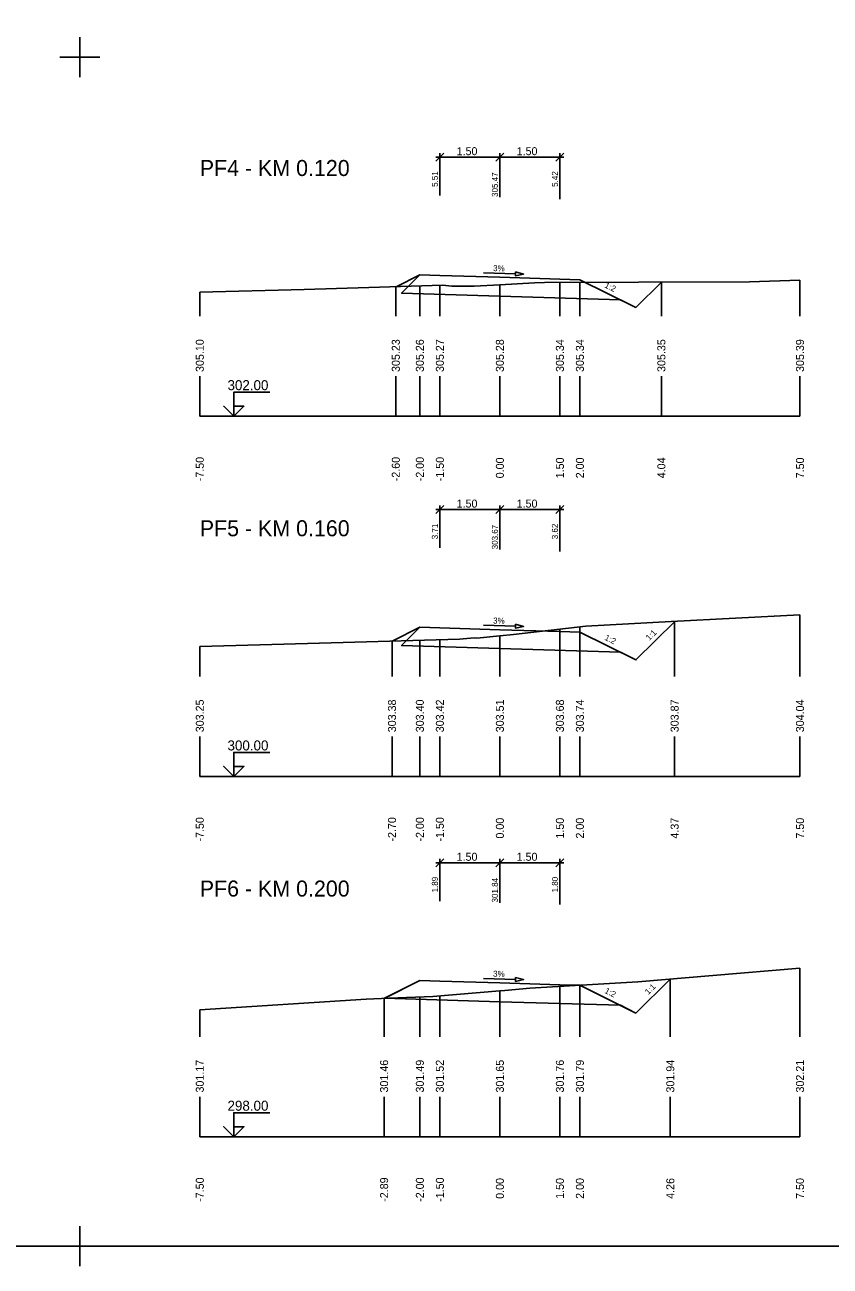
# Model space of a CAD drawing. Extents: x -5 to 1265, y -2 to 602.
# Drawn here: x 196.3 to 397.5, y -2.3 to 307.8 of the extents above; entities that cross this region are included whole.
import ezdxf

# ---------------------------------------------------------------- set-up
doc = ezdxf.new("R2010")
doc.units = 0
for name, color, linetype in [('KOTA', 7, 'Continuous'), ('KOTA_DELKY', 7, 'Continuous'), ('KOTA_DELKY_CONT', 7, 'Continuous'), ('NS_TELESO_VOZOVKY', 7, 'Continuous'), ('NS_V_PF', 7, 'Continuous'), ('REZY_PF_PUVODNI', 7, 'Continuous'), ('SESTAVY_REZU_PF', 7, 'Continuous'), ('SKLON', 7, 'Continuous'), ('SVK', 7, 'Continuous')]:
    doc.layers.add(name, color=color, linetype=linetype)

msp = doc.modelspace()

# ---------------------------------------------------------------- linework, layer by layer
for p, q in [((210, 304.67), (210, 294.67)), ((210, 304.67), (210, 294.67)), ((210, 304.67), (210, 294.67)), ((210, 304.67), (210, 294.67)), ((210, 304.67), (210, 294.67)), ((210, 304.67), (210, 294.67)), ((210, 304.67), (210, 294.67)), ((210, 304.67), (210, 294.67)), ((210, 304.67), (210, 294.67)), ((210, 304.67), (210, 294.67)), ((210, 304.67), (210, 294.67)), ((210, 304.67), (210, 294.67)), ((210, 304.67), (210, 294.67)), ((210, 304.67), (210, 294.67)), ((210, 304.67), (210, 294.67)), ((210, 304.67), (210, 294.67)), ((210, 304.67), (210, 294.67)), ((210, 304.67), (210, 294.67)), ((210, 304.67), (210, 294.67)), ((210, 304.67), (210, 294.67)), ((210, 304.67), (210, 294.67)), ((210, 304.67), (210, 294.67)), ((210, 304.67), (210, 294.67)), ((210, 304.67), (210, 294.67)), ((210, 304.67), (210, 294.67)), ((210, 304.67), (210, 294.67)), ((210, 304.67), (210, 294.67)), ((210, 304.67), (210, 294.67)), ((210, 304.67), (210, 294.67)), ((210, 304.67), (210, 294.67)), ((210, 304.67), (210, 294.67)), ((210, 304.67), (210, 294.67)), ((210, 304.67), (210, 294.67)), ((210, 304.67), (210, 294.67)), ((210, 304.67), (210, 294.67)), ((210, 304.67), (210, 294.67)), ((210, 304.67), (210, 294.67)), ((210, 304.67), (210, 294.67)), ((210, 304.67), (210, 294.67)), ((210, 304.67), (210, 294.67)), ((210, 304.67), (210, 294.67)), ((210, 304.67), (210, 294.67)), ((210, 304.67), (210, 294.67)), ((210, 304.67), (210, 294.67)), ((210, 304.67), (210, 294.67)), ((210, 304.67), (210, 294.67)), ((210, 304.67), (210, 294.67)), ((210, 304.67), (210, 294.67)), ((210, 304.67), (210, 294.67)), ((210, 304.67), (210, 294.67)), ((210, 304.67), (210, 294.67)), ((210, 304.67), (210, 294.67)), ((210, 304.67), (210, 294.67)), ((210, 304.67), (210, 294.67)), ((210, 304.67), (210, 294.67)), ((210, 304.67), (210, 294.67)), ((210, 304.67), (210, 294.67)), ((210, 304.67), (210, 294.67)), ((210, 304.67), (210, 294.67)), ((210, 304.67), (210, 294.67)), ((210, 304.67), (210, 294.67)), ((210, 304.67), (210, 294.67)), ((210, 304.67), (210, 294.67)), ((210, 304.67), (210, 294.67)), ((210, 304.67), (210, 294.67)), ((210, 304.67), (210, 294.67)), ((215, 299.67), (205, 299.67)), ((215, 299.67), (205, 299.67)), ((215, 299.67), (205, 299.67)), ((215, 299.67), (205, 299.67)), ((215, 299.67), (205, 299.67)), ((215, 299.67), (205, 299.67)), ((215, 299.67), (205, 299.67)), ((215, 299.67), (205, 299.67)), ((215, 299.67), (205, 299.67)), ((215, 299.67), (205, 299.67)), ((215, 299.67), (205, 299.67)), ((215, 299.67), (205, 299.67)), ((215, 299.67), (205, 299.67)), ((215, 299.67), (205, 299.67)), ((215, 299.67), (205, 299.67)), ((215, 299.67), (205, 299.67)), ((215, 299.67), (205, 299.67)), ((215, 299.67), (205, 299.67)), ((215, 299.67), (205, 299.67)), ((215, 299.67), (205, 299.67)), ((215, 299.67), (205, 299.67)), ((215, 299.67), (205, 299.67)), ((215, 299.67), (205, 299.67)), ((215, 299.67), (205, 299.67)), ((215, 299.67), (205, 299.67)), ((215, 299.67), (205, 299.67)), ((215, 299.67), (205, 299.67)), ((215, 299.67), (205, 299.67)), ((215, 299.67), (205, 299.67)), ((215, 299.67), (205, 299.67)), ((215, 299.67), (205, 299.67)), ((215, 299.67), (205, 299.67)), ((215, 299.67), (205, 299.67)), ((215, 299.67), (205, 299.67)), ((215, 299.67), (205, 299.67)), ((215, 299.67), (205, 299.67)), ((215, 299.67), (205, 299.67)), ((215, 299.67), (205, 299.67)), ((215, 299.67), (205, 299.67)), ((215, 299.67), (205, 299.67)), ((215, 299.67), (205, 299.67)), ((215, 299.67), (205, 299.67)), ((215, 299.67), (205, 299.67)), ((215, 299.67), (205, 299.67)), ((215, 299.67), (205, 299.67)), ((215, 299.67), (205, 299.67)), ((215, 299.67), (205, 299.67)), ((215, 299.67), (205, 299.67)), ((215, 299.67), (205, 299.67)), ((215, 299.67), (205, 299.67)), ((215, 299.67), (205, 299.67)), ((215, 299.67), (205, 299.67)), ((215, 299.67), (205, 299.67)), ((215, 299.67), (205, 299.67)), ((215, 299.67), (205, 299.67)), ((215, 299.67), (205, 299.67)), ((215, 299.67), (205, 299.67)), ((215, 299.67), (205, 299.67)), ((215, 299.67), (205, 299.67)), ((215, 299.67), (205, 299.67)), ((215, 299.67), (205, 299.67)), ((215, 299.67), (205, 299.67)), ((215, 299.67), (205, 299.67)), ((215, 299.67), (205, 299.67)), ((215, 299.67), (205, 299.67)), ((215, 299.67), (205, 299.67)), ((210, 7.67), (210, -2.33)), ((210, 7.67), (210, -2.33)), ((210, 7.67), (210, -2.33)), ((210, 7.67), (210, -2.33)), ((210, 7.67), (210, -2.33)), ((210, 7.67), (210, -2.33)), ((210, 7.67), (210, -2.33)), ((210, 7.67), (210, -2.33)), ((210, 7.67), (210, -2.33)), ((210, 7.67), (210, -2.33)), ((210, 7.67), (210, -2.33)), ((210, 7.67), (210, -2.33)), ((215, 2.67), (205, 2.67)), ((215, 2.67), (205, 2.67)), ((215, 2.67), (205, 2.67)), ((215, 2.67), (205, 2.67)), ((215, 2.67), (205, 2.67)), ((215, 2.67), (205, 2.67)), ((215, 2.67), (205, 2.67)), ((215, 2.67), (205, 2.67)), ((215, 2.67), (205, 2.67)), ((215, 2.67), (205, 2.67)), ((215, 2.67), (205, 2.67)), ((215, 2.67), (205, 2.67))]:
    msp.add_line(p, q)
msp.add_lwpolyline([(0, 596.67), (1260, 596.67), (1260, 2.67), (0, 2.67)], close=True)
at = {"layer": 'KOTA'}
for points in [[(248.51, 210), (246.01, 212.5), (248.51, 210), (248.51, 216), (257.51, 216)], [(248.51, 210), (251.01, 212.5), (248.51, 212.5), (248.51, 210)], [(248.51, 210), (251.01, 212.5), (248.51, 212.5)], [(248.51, 120), (246.01, 122.5), (248.51, 120), (248.51, 126), (257.51, 126)], [(248.51, 120), (251.01, 122.5), (248.51, 122.5), (248.51, 120)], [(248.51, 120), (251.01, 122.5), (248.51, 122.5)], [(248.51, 30), (246.01, 32.5), (248.51, 30), (248.51, 36), (257.51, 36)], [(248.51, 30), (251.01, 32.5), (248.51, 32.5), (248.51, 30)], [(248.51, 30), (251.01, 32.5), (248.51, 32.5)]]:
    msp.add_lwpolyline(points, dxfattribs=at)
at = {"layer": 'KOTA_DELKY'}
for points in [[(299, 273.7), (301, 275.7)], [(299, 274.7), (316, 274.7)], [(300, 265.15), (300, 275.7)], [(314, 273.7), (316, 275.7)], [(314, 273.7), (316, 275.7)], [(314, 274.7), (331, 274.7)], [(315, 264.7), (315, 275.7)], [(315, 264.7), (315, 275.7)], [(329, 273.7), (331, 275.7)], [(330, 264.25), (330, 275.7)], [(299, 185.66), (301, 187.66)], [(299, 186.66), (316, 186.66)], [(300, 177.11), (300, 187.66)], [(314, 185.66), (316, 187.66)], [(314, 185.66), (316, 187.66)], [(314, 186.66), (331, 186.66)], [(315, 176.66), (315, 187.66)], [(315, 176.66), (315, 187.66)], [(329, 185.66), (331, 187.66)], [(330, 176.21), (330, 187.66)], [(299, 97.44), (301, 99.44)], [(300, 88.89), (300, 99.44)], [(314, 97.44), (316, 99.44)], [(314, 97.44), (316, 99.44)], [(315, 88.44), (315, 99.44)], [(315, 88.44), (315, 99.44)], [(329, 97.44), (331, 99.44)], [(330, 87.99), (330, 99.44)], [(299, 98.44), (316, 98.44)], [(314, 98.44), (331, 98.44)]]:
    msp.add_lwpolyline(points, dxfattribs=at)
at = {"layer": 'NS_TELESO_VOZOVKY'}
for points in [[(315, 244.7), (330, 244.25), (335, 244.1), (349.01, 237.17), (345.11, 239.09), (315, 240), (290.44, 240.73), (295, 245.3), (300, 245.15), (315, 244.7)], [(315, 156.66), (330, 156.21), (335, 156.06), (349.01, 149.13), (345.11, 151.06), (315, 151.96), (290.44, 152.7), (295, 157.26), (300, 157.11), (315, 156.66)], [(315, 68.44), (330, 67.99), (335, 67.84), (349.01, 60.91), (345.11, 62.84), (315, 63.74), (286.13, 64.61), (295, 69.04), (300, 68.89), (315, 68.44)]]:
    msp.add_lwpolyline(points, dxfattribs=at)
at = {"layer": 'NS_V_PF'}
for points in [[(289.1, 242.35), (295, 245.3), (300, 245.15), (315, 244.7), (330, 244.25), (335, 244.1), (349.01, 237.17), (355.42, 243.51)], [(288.1, 153.81), (295, 157.26), (300, 157.11), (315, 156.66), (330, 156.21), (335, 156.06), (349.01, 149.13), (358.71, 158.73)], [(286.05, 64.57), (295, 69.04), (300, 68.89), (315, 68.44), (330, 67.99), (335, 67.84), (349.01, 60.91), (357.58, 69.39)]]:
    msp.add_lwpolyline(points, dxfattribs=at)
at = {"layer": 'REZY_PF_PUVODNI'}
for points in [[(240, 240.97), (266.07, 241.67), (282.21, 242.11), (300.73, 242.76), (302.98, 242.48), (308.56, 242.48), (315, 242.84), (315, 242.84), (323.66, 243.33), (326.17, 243.39), (349.65, 243.48), (377.36, 243.59), (390, 243.94)], [(240, 152.5), (258, 152.95), (275.82, 153.46), (304.88, 154.29), (308.54, 154.6), (309.27, 154.54), (315, 155.12), (315, 155.12), (318.41, 155.47), (336.49, 157.58), (357.82, 158.68), (390, 160.35)], [(240, 61.74), (281.56, 64.38), (287.32, 64.62), (298.21, 65.07), (315, 66.45), (315, 66.45), (316.2, 66.55), (322.52, 67.15), (349.49, 68.72), (368.23, 70.28), (390, 72.1)]]:
    msp.add_lwpolyline(points, dxfattribs=at)
at = {"layer": 'SESTAVY_REZU_PF'}
for points in [[(240, 210), (390, 210)], [(240, 120), (390, 120)], [(240, 30), (390, 30)]]:
    msp.add_lwpolyline(points, dxfattribs=at)
at = {"layer": 'SKLON'}
for points in [[(310.92, 245.82), (318.91, 245.58)], [(318.93, 246.08), (320.91, 245.52), (318.9, 245.08), (318.93, 246.08)], [(310.92, 157.78), (318.91, 157.55)], [(318.93, 158.04), (320.91, 157.49), (318.9, 157.05), (318.93, 158.04)], [(310.92, 69.56), (318.91, 69.32)], [(318.93, 69.82), (320.91, 69.26), (318.9, 68.82), (318.93, 69.82)]]:
    msp.add_lwpolyline(points, dxfattribs=at)
for points in [[(318.93, 246.08), (320.91, 245.52), (318.9, 245.08)], [(318.93, 158.04), (320.91, 157.49), (318.9, 157.05)], [(318.93, 69.82), (320.91, 69.26), (318.9, 68.82)]]:
    msp.add_lwpolyline(points, close=True, dxfattribs=at)
at = {"layer": 'SVK'}
for points in [[(288.99, 235), (288.99, 242.34)], [(295, 235), (295, 242.56)], [(300, 235), (300, 242.73)], [(315, 235), (315, 242.84)], [(330, 235), (330, 243.41)], [(335, 235), (335, 243.43)], [(355.36, 235), (355.36, 243.51)], [(390, 235), (390, 243.94)], [(240, 235), (240, 240.97)], [(240, 210), (240, 220)], [(288.99, 210), (288.99, 220)], [(295, 210), (295, 220)], [(300, 210), (300, 220)], [(315, 210), (315, 220)], [(330, 210), (330, 220)], [(335, 210), (335, 220)], [(355.36, 210), (355.36, 220)], [(390, 210), (390, 220)], [(358.67, 145), (358.67, 158.73)], [(390, 145), (390, 160.35)], [(315, 145), (315, 155.12)], [(330, 145), (330, 156.82)], [(335, 145), (335, 157.4)], [(240, 145), (240, 152.5)], [(288.04, 145), (288.04, 153.81)], [(295, 145), (295, 154.01)], [(300, 145), (300, 154.15)], [(240, 120), (240, 130)], [(288.04, 120), (288.04, 130)], [(295, 120), (295, 130)], [(300, 120), (300, 130)], [(315, 120), (315, 130)], [(330, 120), (330, 130)], [(335, 120), (335, 130)], [(358.67, 120), (358.67, 130)], [(390, 120), (390, 130)], [(390, 55), (390, 72.1)], [(357.59, 55), (357.59, 69.39)], [(300, 55), (300, 65.22)], [(315, 55), (315, 66.45)], [(330, 55), (330, 67.59)], [(335, 55), (335, 67.88)], [(286.06, 55), (286.06, 64.57)], [(295, 55), (295, 64.94)], [(240, 55), (240, 61.74)], [(240, 30), (240, 40)], [(286.06, 30), (286.06, 40)], [(295, 30), (295, 40)], [(300, 30), (300, 40)], [(315, 30), (315, 40)], [(330, 30), (330, 40)], [(335, 30), (335, 40)], [(357.59, 30), (357.59, 40)], [(390, 30), (390, 40)]]:
    msp.add_lwpolyline(points, dxfattribs=at)

# ---------------------------------------------------------------- texts
at = {"layer": 'KOTA'}
for s, p in [('302.00', (246.93, 216.5)), ('300.00', (246.93, 126.5)), ('298.00', (246.93, 36.5))]:
    msp.add_text(s, height=2.5, dxfattribs=at).set_placement(p)
at = {"layer": 'KOTA_DELKY'}
for p in [(304.19, 275.2), (319.19, 275.2), (304.19, 187.16), (319.19, 187.16), (304.19, 98.94), (319.19, 98.94)]:
    msp.add_text('1.50', height=2, dxfattribs=at).set_placement(p)
at = {"layer": 'KOTA_DELKY_CONT'}
for s, p in [('5.51', (299.5, 267.29)), ('305.47', (314.5, 264.77)), ('5.42', (329.5, 267.29)), ('3.71', (299.5, 179.25)), ('3.62', (329.5, 179.25)), ('303.67', (314.5, 176.74)), ('1.89', (299.5, 91.03)), ('301.84', (314.5, 88.52)), ('1.80', (329.5, 91.03))]:
    msp.add_text(s, height=1.5, rotation=90, dxfattribs=at).set_placement(p)
at = {"layer": 'SESTAVY_REZU_PF'}
for s, p in [('PF4 - KM 0.120', (240, 270)), ('PF5 - KM 0.160', (240, 180)), ('PF6 - KM 0.200', (240, 90))]:
    msp.add_text(s, height=4, dxfattribs=at).set_placement(p)
at = {"layer": 'SKLON'}
for s, rotation, p in [('3%', 358.2816, (313.29, 246.25)), ('1:2', 333.679, (341.04, 242.23)), ('3%', 358.2816, (313.29, 158.21)), ('1:2', 333.679, (341.04, 154.19)), ('1:1', 44.7149, (352.33, 153.83)), ('3%', 358.2816, (313.29, 69.99)), ('1:2', 333.679, (341.04, 65.97)), ('1:1', 44.7149, (352.1, 65.37))]:
    msp.add_text(s, height=1.5, rotation=rotation, dxfattribs=at).set_placement(p)
at = {"layer": 'SVK'}
for s, p in [(' 305.10', (241, 220.3)), (' 305.23', (289.99, 220.3)), (' 305.26', (296, 220.3)), (' 305.27', (301, 220.3)), (' 305.28', (316, 220.3)), (' 305.34', (331, 220.3)), (' 305.34', (336, 220.3)), (' 305.35', (356.36, 220.3)), (' 305.39', (391, 220.3)), (' -7.50', (241, 193)), (' -2.60', (289.99, 193)), (' -2.00', (296, 193)), (' -1.50', (301, 193)), ('  0.00', (316, 193)), ('  1.50', (331, 193)), ('  2.00', (336, 193)), ('  4.04', (356.36, 193)), ('  7.50', (391, 193)), (' 303.25', (241, 130.3)), (' 303.38', (289.04, 130.3)), (' 303.40', (296, 130.3)), (' 303.42', (301, 130.3)), (' 303.51', (316, 130.3)), (' 303.68', (331, 130.3)), (' 303.74', (336, 130.3)), (' 303.87', (359.67, 130.3)), (' 304.04', (391, 130.3)), (' -7.50', (241, 103)), (' -2.70', (289.04, 103)), (' -2.00', (296, 103)), (' -1.50', (301, 103)), ('  0.00', (316, 103)), ('  1.50', (331, 103)), ('  2.00', (336, 103)), ('  4.37', (359.67, 103)), ('  7.50', (391, 103)), (' 301.17', (241, 40.3)), (' 301.46', (287.06, 40.3)), (' 301.49', (296, 40.3)), (' 301.52', (301, 40.3)), (' 301.65', (316, 40.3)), (' 301.76', (331, 40.3)), (' 301.79', (336, 40.3)), (' 301.94', (358.59, 40.3)), (' 302.21', (391, 40.3)), (' -7.50', (241, 13)), (' -2.89', (287.06, 13)), (' -2.00', (296, 13)), (' -1.50', (301, 13)), ('  0.00', (316, 13)), ('  1.50', (331, 13)), ('  2.00', (336, 13)), ('  4.26', (358.59, 13)), ('  7.50', (391, 13))]:
    msp.add_text(s, height=2, rotation=90, dxfattribs=at).set_placement(p)

doc.saveas('drawing.dxf')
